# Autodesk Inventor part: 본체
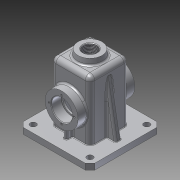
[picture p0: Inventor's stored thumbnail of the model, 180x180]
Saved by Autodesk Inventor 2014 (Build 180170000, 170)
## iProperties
Created: 2017-08
Part Number: 본체
Material: 알루미늄 6061
Document SubType Name: Modeling
Designer: user
Density: 2.71 g/cm^3
Appearance: 알루미늄 - 평지
Mass: 797.269 g
Surface Area: 899.907 cm^2
Volume: 294.195 cm^3
Author: user
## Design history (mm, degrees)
sketch "스케치1"
  geometry: L1 (32.5, 32.5)-(-32.5, 32.5); L2 (-32.5, 32.5)-(-32.5, -32.5); L3 (-32.5, -32.5)-(32.5, -32.5); L4 (32.5, -32.5)-(32.5, 32.5); L5 (32.5, 32.5)-(-32.5, -32.5); L6 (-32.5, 32.5)-(32.5, -32.5); 1 further point
  constraints: 12 end point, 2 midpoint, 2 parallel, 2 perpendicular, 1 horizontal
  dimensions: "d0" = 65 distance of L1.start L1.end
extrude "돌출1" new body sketch "스케치1" distance "d1" = 110; taper "d2" = 0 deg
fillet "모깎기1" dims "d3" = 8
fillet "모깎기2" dims "d4" = 8
feature "쉘1" dims "d5" = 5
node "작업 평면2"
sketch "스케치4"
  geometry: C1 r 27.5 at (24.5, 55); 1 further point
  constraints: 1 centre point, 1 vertical alignment
  dimensions: "d9" = 55 distance of point (24.5, 0) C1.centre; "d10" = 55 diameter of C1
extrude "돌출2" join sketch "스케치4" stored distance "d11" = 110; taper "d12" = 0 deg
hole "구멍1" diameter "d15" = 30; stored, may be unused: countersink angle "d19" = 90 deg, drill point angle "d21" = 118 deg; dims "d13" = 10, "d14" = 10, "d16" = 6, "d17" = 35, "d18" = 17, "d20" = 8
sketch "스케치5"
  geometry: L1 (-24.5, 32.5)-(24.5, 32.5) reference; L2 (-32.5, -24.5)-(-32.5, 24.5) reference; L3 (24.5, -32.5)-(-24.5, -32.5) reference; L4 (32.5, 24.5)-(32.5, -24.5) reference; L5 (-60, 60)-(60, 60); L6 (60, 60)-(60, -60); L7 (60, -60)-(-60, -60); L8 (-60, -60)-(-60, 60); L9 (-60, 60)-(60, -60); L10 (60, 60)-(-60, -60); A1 r 8 centre (24.5, 24.5) between (32.5, 24.5) and (24.5, 32.5) reference; A2 r 8 centre (-24.5, 24.5) between (-24.5, 32.5) and (-32.5, 24.5) reference; A3 r 8 centre (-24.5, -24.5) between (-32.5, -24.5) and (-24.5, -32.5) reference; A4 r 8 centre (24.5, -24.5) between (24.5, -32.5) and (32.5, -24.5) reference; 1 further point
  constraints: 12 end point, 2 midpoint, 2 parallel, 2 perpendicular, 1 horizontal
  dimensions: "d22" = 120 distance of L7.end L5.start
extrude "돌출3" join sketch "스케치5" distance "d23" = 10; taper "d24" = 0 deg
sketch "스케치6"
  geometry: L1 (32.5, 102)-(32.5, 10) reference; L2 (32.5, 10)-(60, 10) reference; L3 (60, 10)-(60, 0) reference; L4 (60, 0)-(27.5, 0) reference; L5 (27.5, 0)-(27.5, 102) reference; L6 (24.5, 105)-(-24.5, 105) reference; L7 (-27.5, 102)-(-27.5, 0) reference; L8 (-27.5, 0)-(-60, 0) reference; L9 (-60, 0)-(-60, 10) reference; L10 (-60, 10)-(-32.5, 10) reference; L11 (-32.5, 10)-(-32.5, 102) reference; L12 (-24.5, 110)-(24.5, 110) reference; L13 (48, 10)-(32.5, 97.905); A1 r 8 centre (24.5, 102) between (32.5, 102) and (24.5, 110) reference; A2 r 3 centre (24.5, 102) between (27.5, 102) and (24.5, 105) reference; A3 r 3 centre (-24.5, 102) between (-24.5, 105) and (-27.5, 102) reference; A4 r 8 centre (-24.5, 102) between (-24.5, 110) and (-32.5, 102) reference; 1 further point
  constraints: 2 end point, 2 point on line
  dimensions: "d25" = 10 deg angle of L3 L13; "d26" = 12 distance from line of L3 L13.start
feature "리브1" sketch "스케치6" dims "d27" = 1, "d28" = 10, "d29" = 0, "d30" = 0, "d31" = 1, "d32" = 1
sketch "스케치7"
  geometry: L1 (30.5, 40)-(30.5, 37.5) reference; L2 (30.5, 37.5)-(47.5, 37.5) reference; L3 (47.5, 37.5)-(47.5, 27.5) reference; L4 (47.5, 27.5)-(32.5, 27.5) reference; L5 (32.5, 27.5)-(32.5, 10) reference; L6 (32.5, 10)-(60, 10) reference; L7 (60, 10)-(60, 0) reference; L8 (60, 0)-(27.5, 0) reference; L9 (27.5, 0)-(27.5, 40) reference; L10 (27.5, 40)-(30.5, 40) reference; L11 (-47.5, 82.5)-(-32.5, 82.5) reference; L12 (-32.5, 82.5)-(-32.5, 102) reference; L13 (-24.5, 110)-(24.5, 110) reference; L14 (32.5, 102)-(32.5, 82.5) reference; L15 (32.5, 82.5)-(47.5, 82.5) reference; L16 (47.5, 82.5)-(47.5, 72.5) reference; L17 (47.5, 72.5)-(30.5, 72.5) reference; L18 (30.5, 72.5)-(30.5, 70) reference; L19 (30.5, 70)-(27.5, 70) reference; L20 (27.5, 70)-(27.5, 102) reference; L21 (24.5, 105)-(-24.5, 105) reference; L22 (-27.5, 102)-(-27.5, 70) reference; L23 (-27.5, 70)-(-30.5, 70) reference; L24 (-30.5, 70)-(-30.5, 72.5) reference; L25 (-30.5, 72.5)-(-47.5, 72.5) reference; L26 (-47.5, 72.5)-(-47.5, 82.5) reference; L27 (-32.5, 27.5)-(-47.5, 27.5) reference; L28 (-47.5, 27.5)-(-47.5, 37.5) reference; L29 (-47.5, 37.5)-(-30.5, 37.5) reference; L30 (-30.5, 37.5)-(-30.5, 40) reference; L31 (-30.5, 40)-(-27.5, 40) reference; L32 (-27.5, 40)-(-27.5, 0) reference; L33 (-27.5, 0)-(-60, 0) reference; L34 (-60, 0)-(-60, 10) reference; L35 (-60, 10)-(-32.5, 10) reference; L36 (-32.5, 10)-(-32.5, 27.5) reference; L37 (-42.5, 27.5)-(-42.5, 10); A1 r 8 centre (-24.5, 102) between (-24.5, 110) and (-32.5, 102) reference; A2 r 8 centre (24.5, 102) between (32.5, 102) and (24.5, 110) reference; A3 r 3 centre (24.5, 102) between (27.5, 102) and (24.5, 105) reference; A4 r 3 centre (-24.5, 102) between (-24.5, 105) and (-27.5, 102) reference; 1 further point
  constraints: 2 end point, 2 point on line, 1 perpendicular
  dimensions: "d33" = 15 distance between parallel lines of L32 L37
feature "리브2" sketch "스케치7" dims "d34" = 1, "d35" = 6, "d36" = 0, "d37" = 0, "d38" = 1, "d39" = 1
node "작업 평면3"
sketch "스케치8"
  geometry: C1 r 20 at (0, 0); 1 further point
  constraints: 1 centre point, 1 coincident
  dimensions: "d41" = 40 diameter of C1
extrude "돌출4" join sketch "스케치8" stored distance "d42" = 10; taper "d43" = 7 deg
hole "구멍2" diameter "d46" = 22.835; stored, may be unused: countersink angle "d50" = 90 deg, drill point angle "d52" = 118 deg; dims "d44" = 10, "d45" = 10, "d47" = 6, "d48" = 35, "d49" = 17, "d51" = 8
sketch "스케치9"
  geometry: L1 (60, -60)-(60, 60) reference; L2 (60, 60)-(-60, 60) reference; 2 further points
  dimensions: "d53" = 12.5 distance from line of L2 point (47.5, 47.5); "d54" = 12.5 distance from line of L1 point (47.5, 47.5)
hole "구멍3" sketch "스케치9" at (47.5, 47.5) diameter "d57" = 10; stored, may be unused: countersink angle "d61" = 90 deg, drill point angle "d63" = 118 deg; dims "d58" = 6, "d59" = 35, "d60" = 17, "d62" = 8
chamfer "모따기1" distance "d70" = 8; stored, may be unused: second distance "d71" = 2, angle "d72" = 45 deg
sketch "스케치10"
  geometry: C1 r 17.5 at (0, 0) reference; 2 further points
  constraints: 1 vertical alignment
  dimensions: "d73" = 21 distance of C1.centre point (0, 21)
hole "구멍4" sketch "스케치10" at (0, 21) diameter "d74" = 3.242; stored, may be unused: countersink angle "d78" = 90 deg, drill point angle "d80" = 118 deg; dims "d75" = 8, "d76" = 35, "d77" = 17, "d79" = 10
chamfer "모따기2" distance "d84" = 1; stored, may be unused: second distance "d85" = 2, angle "d86" = 45 deg
fillet "모깎기3" dims "d87" = 0.3
fillet "모깎기5" dims "d89" = 3
fillet "모깎기6" dims "d90" = 3
fillet "모깎기7" dims "d91" = 3
fillet "모깎기8" dims "d92" = 3
fillet "모깎기9" dims "d93" = 1
fillet "모깎기10" dims "d94" = 3
sketch "스케치11"
  geometry: L1 (57, 0)-(57, 91) reference; L2 (44.5, -18)-(4.5, -18) reference; 2 further points
  constraints: 1 other
  dimensions: "d95" = 32.5 distance from line of L1 point (24.5, 8); "d96" = 26 distance from line of L2 point (24.5, 8)
feature "엠보싱1" sketch "스케치11" dims "d97" = 0.5, "d98" = 0
chamfer "모따기3" distance "d99" = 1; stored, may be unused: second distance "d100" = 2, angle "d101" = 45 deg
node "솔리드1"
mirror "대칭1"
mirror "대칭2"
mirror "대칭3"
pattern_linear "직사각형 패턴1" dims "d66" = 95, "d69" = 95
pattern_circular "원형 패턴1" dims angle "d82" = 360 deg
mirror "대칭4"
node "절단 모서리 투영1"
node "절단 모서리 투영2"
other parameters: "d8" = 15
